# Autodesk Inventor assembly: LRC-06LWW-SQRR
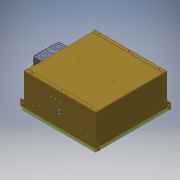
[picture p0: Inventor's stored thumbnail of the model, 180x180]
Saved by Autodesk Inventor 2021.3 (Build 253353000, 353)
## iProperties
Part Number: LRC-06LWW-SQRR
Document SubType Name: Assembly
Designer: JChurch
Author: JChurch
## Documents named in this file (5)
- X:\Revit Files\0000-Un-Zipped\COB\LRC-06LWW-SQR\LRC-06LWW-SQRR.iam
- X:\INVENTOR\830\830376-00-00.iam
- X:\INVENTOR\881\881088-00-00.iam
- X:\INVENTOR\700\700466-25-XX (NEW).iam
- X:\INVENTOR\725\725267-00-00.ipt
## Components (4 placed, 4 different names)
1. 830376-00-00:1 [sub-assembly] — Mate:1, Mate:2, Flush:1, Tangent:1, Angle:1, Mate:5
2. 881088-00-00:1 [sub-assembly] — Mate:3, Tangent:1, Angle:1
3. 700466-25-XX (NEW):1 [sub-assembly] — Mate:4, Flush:2, Mate:5, Mate:6, Mate:7, Mate:8
4. 725267-00-00:1 — Mate:6, Mate:7, Mate:8
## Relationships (12: Mate 8, Flush 2, Tangent 1, Angle 1)
- Mate:1: 830376-00-00:1
- Mate:2: 830376-00-00:1
- Flush:1: 830376-00-00:1
- Mate:3: 881088-00-00:1
- Tangent:1: 830376-00-00:1 ↔ 881088-00-00:1
- Angle:1: 830376-00-00:1 ↔ 881088-00-00:1
- Mate:4: 700466-25-XX (NEW):1
- Flush:2: 700466-25-XX (NEW):1
- Mate:5: 830376-00-00:1 ↔ 700466-25-XX (NEW):1
- Mate:6: 700466-25-XX (NEW):1 ↔ 725267-00-00:1
- Mate:7: 700466-25-XX (NEW):1 ↔ 725267-00-00:1
- Mate:8: 700466-25-XX (NEW):1 ↔ 725267-00-00:1
